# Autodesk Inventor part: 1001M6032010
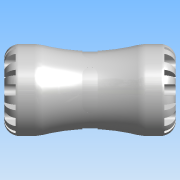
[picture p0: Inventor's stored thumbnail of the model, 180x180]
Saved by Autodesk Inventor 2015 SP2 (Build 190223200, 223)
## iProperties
Created: 2016-12
Part Number: 1001M6032010
Material: PVC-Piping
Description: PLASSON COUPLER METRIC TO IMPERIAL 32X1" SERIES 1
Document SubType Name: Modeling
Designer: KIM
Mass: 95.2094 g
Surface Area: 200.83 cm^2
Volume: 68.0067 cm^3
Density: 1.4 g/cm^3
Appearance: Smooth - White
ILogicFactory: False
Author: KIM
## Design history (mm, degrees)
derived "1001M.ipt"
feature "Solid1::1001M.ipt"
tag "TaggingFeature1"
body "Solid1"
other parameters: "d2" = 53, "d11" = 7.2, "d13" = 7.2, "d14" = 0, "d16" = 360 deg, "d18" = 8 deg, "d19" = 0.64, "d20" = 8 deg, "d21" = 0.64, "d23" = 0, "d25" = 360 deg, "d27" = 23.2, "d28" = 9.6, "d29" = 9.6, "d30" = 14.112, "d31" = 0, "d33" = 0, "d37" = 21.6, "d38" = 0.58, "d44" = 32, "d45" = 21.6, "d46" = 49.3, "d47" = 58, "d50" = 360 deg, "d54" = 0.513, "d64" = 108, "d66" = 2.11667, "d67" = 54, "d70" = 7.2, "d72" = 7.2, "d73" = 0, "d75" = 360 deg, "d77" = 8 deg, "d78" = 8 deg, "d79" = 0.64, "d80" = 0.64, "d82" = 0, "d84" = 360 deg, "d93" = 25.4, "d_" = 32, "E_" = 58, "H_" = 108, "l_" = 53, "d_1" = 25.4, "d42" = 58, "d52" = 9, "d68" = 58, "d71" = 9
